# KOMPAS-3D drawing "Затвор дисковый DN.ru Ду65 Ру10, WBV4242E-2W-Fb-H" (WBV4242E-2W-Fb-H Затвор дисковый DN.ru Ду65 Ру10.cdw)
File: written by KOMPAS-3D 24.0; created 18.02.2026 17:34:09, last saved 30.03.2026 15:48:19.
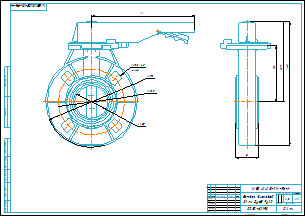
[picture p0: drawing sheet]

Document properties: Автор: R2D2; Форматы листов документа: A2; Полное имя файла: WBV4242E-2W-Fb-H Затвор дисковый DN.ru Ду65 Ру10.m3d; Масса: 1.31; Наименование: Затвор дисковый DN.ru Ду65 Ру10; Количество листов документа: 1; Примечание: D050-81198

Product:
- Part/product: Затвор дисковый DN.ru Ду65 Ру10  | designation WBV4242E-2W-Fb-H
    Масса: 1.31
    Раздел спецификации: Прочие изделия
    Примечание: D050-81198

Views: Вид 1, Спереди, Проекционный вид 2
Referenced files in E:\Работа\Зайцев\WBV4242E-2W-Fb-ISO Затвор дисковый DN.ru Ду50-200 Ру10\DN50\: WBV4242E-2W-Fb-ISO Затвор дисковый DN.ru Ду50 Ру10.m3d
Referenced files in E:\Работа\Зайцев\WBV4242E-2W-Fb-H Затвор дисковый DN.ru Ду50-200 Ру10\DN65\: WBV4242E-2W-Fb-H Затвор дисковый DN.ru Ду65 Ру10.m3d
Referenced files in E:\Работа\Зайцев\Для компаса\: чертеж DN.ru А3.cdt
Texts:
  WBV4242E-2W-Fb-H
  чертеж DN.ru А3.cdt
  Затвор дисковый
  DN.ru Ду65 Ру10
  Затвор дисковый DN.ru Ду65 Ру10
  WBV4242E-2W-Fb-H Затвор дисковый DN.ru Ду65 Ру10
Dimensions and other numbers on the sheet: 0; 3; 2; 4; 4 отв.; 202; 179; 65; 45; 157; 110; 243; 130,5; 1:1; 1; 1,31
